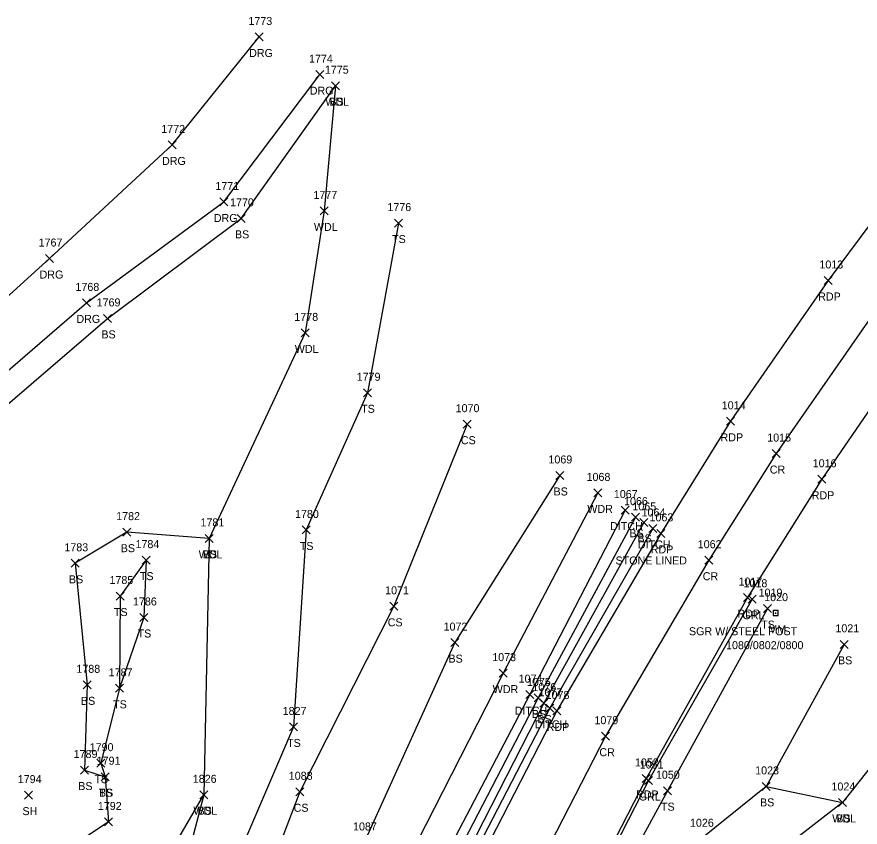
# Model space of a CAD drawing. Extents: x 1551995 to 1555700, y 777276 to 783130.
# Drawn here: x 1554855.8 to 1555066.5, y 778211.4 to 778413.8 of the extents above; entities that cross this region are included whole.
import ezdxf

# ---------------------------------------------------------------- set-up
doc = ezdxf.new("R2010")
doc.units = 0
for name, color, linetype in [('D_A', 7, 'Continuous'), ('D_C', 7, 'Continuous'), ('D_I', 7, 'Continuous'), ('D_TIC', 7, 'Continuous'), ('DD', 7, 'Continuous'), ('L_A', 7, 'Continuous'), ('L_I', 7, 'Continuous'), ('L_TIC', 7, 'Continuous'), ('LAWA', 7, 'Continuous'), ('LELB', 7, 'Continuous'), ('P_A', 7, 'Continuous'), ('P_I', 7, 'Continuous'), ('P_TIC', 7, 'Continuous'), ('PET', 7, 'Continuous'), ('PRC', 7, 'Continuous'), ('R_A', 7, 'Continuous'), ('R_C', 7, 'Continuous'), ('R_I', 7, 'Continuous'), ('R_TIC', 7, 'Continuous'), ('RDG', 7, 'Continuous'), ('RGR', 7, 'Continuous'), ('S_A', 7, 'Continuous'), ('S_C', 7, 'Continuous'), ('S_I', 7, 'Continuous'), ('SRM', 7, 'Continuous')]:
    doc.layers.add(name, color=color, linetype=linetype)

msp = doc.modelspace()

# ---------------------------------------------------------------- linework, layer by layer
at = {"layer": 'D_TIC'}
for points in [[(1555006.77, 778289.58), (1555008.77, 778291.58)], [(1555008.77, 778289.58), (1555006.77, 778291.58)], [(1555013.72, 778284.98), (1555015.72, 778286.98)], [(1555015.72, 778284.98), (1555013.72, 778286.98)], [(1554982.94, 778243.46), (1554984.94, 778245.46)], [(1554984.94, 778243.46), (1554982.94, 778245.46)], [(1554987.93, 778240.04), (1554989.93, 778242.04)], [(1554989.93, 778240.04), (1554987.93, 778242.04)]]:
    msp.add_lwpolyline(points, dxfattribs=at)
at = {"layer": 'DD'}
for points in [[(1555007.77, 778290.58), (1554983.94, 778244.46), (1554960.71, 778200.12), (1554946.97, 778167.91), (1554938.22, 778146.67)], [(1555014.72, 778285.98), (1554988.93, 778241.04), (1554966.26, 778197.38), (1554951.47, 778164.91), (1554943.03, 778145), (1554942.04, 778145.43), (1554940.77, 778145.78), (1554938.22, 778146.67)]]:
    msp.add_lwpolyline(points, dxfattribs=at)
at = {"layer": 'L_TIC'}
for points in [[(1554934.43, 778395.62), (1554936.43, 778397.62)], [(1554936.43, 778395.62), (1554934.43, 778397.62)], [(1554934.43, 778395.62), (1554936.43, 778397.62)], [(1554936.43, 778395.62), (1554934.43, 778397.62)], [(1554931.57, 778364.34), (1554933.57, 778366.34)], [(1554933.57, 778364.34), (1554931.57, 778366.34)], [(1554910.83, 778362.48), (1554912.83, 778364.48)], [(1554912.83, 778362.48), (1554910.83, 778364.48)], [(1554950.12, 778361.3), (1554952.12, 778363.3)], [(1554952.12, 778361.3), (1554950.12, 778363.3)], [(1554877.45, 778337.48), (1554879.45, 778339.48)], [(1554879.45, 778337.48), (1554877.45, 778339.48)], [(1554926.8, 778333.86), (1554928.8, 778335.86)], [(1554928.8, 778333.86), (1554926.8, 778335.86)], [(1554942.39, 778318.89), (1554944.39, 778320.89)], [(1554944.39, 778318.89), (1554942.39, 778320.89)], [(1554967.28, 778311.04), (1554969.28, 778313.04)], [(1554969.28, 778311.04), (1554967.28, 778313.04)], [(1554990.44, 778298.23), (1554992.44, 778300.23)], [(1554992.44, 778298.23), (1554990.44, 778300.23)], [(1554999.96, 778293.87), (1555001.96, 778295.87)], [(1555001.96, 778293.87), (1554999.96, 778295.87)], [(1555009.39, 778287.8), (1555011.39, 778289.8)], [(1555011.39, 778287.8), (1555009.39, 778289.8)], [(1555011.41, 778286.51), (1555013.41, 778288.51)], [(1555013.41, 778286.51), (1555011.41, 778288.51)], [(1554882.27, 778284.06), (1554884.27, 778286.06)], [(1554884.27, 778284.06), (1554882.27, 778286.06)], [(1554927.06, 778284.61), (1554929.06, 778286.61)], [(1554929.06, 778284.61), (1554927.06, 778286.61)], [(1554902.79, 778282.5), (1554904.79, 778284.5)], [(1554904.79, 778282.5), (1554902.79, 778284.5)], [(1554902.79, 778282.5), (1554904.79, 778284.5)], [(1554904.79, 778282.5), (1554902.79, 778284.5)], [(1554869.33, 778276.28), (1554871.33, 778278.28)], [(1554871.33, 778276.28), (1554869.33, 778278.28)], [(1554887.1, 778277.07), (1554889.1, 778279.07)], [(1554889.1, 778277.07), (1554887.1, 778279.07)], [(1554887.1, 778277.07), (1554889.1, 778279.07)], [(1554889.1, 778277.07), (1554887.1, 778279.07)], [(1554880.6, 778268.1), (1554882.6, 778270.1)], [(1554882.6, 778268.1), (1554880.6, 778270.1)], [(1554949, 778265.53), (1554951, 778267.53)], [(1554951, 778265.53), (1554949, 778267.53)], [(1555042.36, 778264.96), (1555044.36, 778266.96)], [(1555044.36, 778264.96), (1555042.36, 778266.96)], [(1554886.53, 778262.74), (1554888.53, 778264.74)], [(1554888.53, 778262.74), (1554886.53, 778264.74)], [(1554964.18, 778256.46), (1554966.18, 778258.46)], [(1554966.18, 778256.46), (1554964.18, 778258.46)], [(1555061.53, 778256.03), (1555063.53, 778258.03)], [(1555063.53, 778256.03), (1555061.53, 778258.03)], [(1554976.33, 778248.83), (1554978.33, 778250.83)], [(1554978.33, 778248.83), (1554976.33, 778250.83)], [(1554872.34, 778245.91), (1554874.34, 778247.91)], [(1554874.34, 778245.91), (1554872.34, 778247.91)], [(1554880.41, 778245.04), (1554882.41, 778247.04)], [(1554882.41, 778245.04), (1554880.41, 778247.04)], [(1554880.41, 778245.04), (1554882.41, 778247.04)], [(1554882.41, 778245.04), (1554880.41, 778247.04)], [(1554985.01, 778242.63), (1554987.01, 778244.63)], [(1554987.01, 778242.63), (1554985.01, 778244.63)], [(1554986.42, 778241.35), (1554988.42, 778243.35)], [(1554988.42, 778241.35), (1554986.42, 778243.35)], [(1554923.89, 778235.39), (1554925.89, 778237.39)], [(1554925.89, 778235.39), (1554923.89, 778237.39)], [(1554875.74, 778226.33), (1554877.74, 778228.33)], [(1554877.74, 778226.33), (1554875.74, 778228.33)], [(1554871.65, 778224.62), (1554873.65, 778226.62)], [(1554873.65, 778224.62), (1554871.65, 778226.62)], [(1554876.84, 778222.95), (1554878.84, 778224.95)], [(1554878.84, 778222.95), (1554876.84, 778224.95)], [(1554876.84, 778222.95), (1554878.84, 778224.95)], [(1554878.84, 778222.95), (1554876.84, 778224.95)], [(1554925.49, 778219.19), (1554927.49, 778221.19)], [(1554927.49, 778219.19), (1554925.49, 778221.19)], [(1555017.33, 778219.45), (1555019.33, 778221.45)], [(1555019.33, 778219.45), (1555017.33, 778221.45)], [(1555042.05, 778220.53), (1555044.05, 778222.53)], [(1555044.05, 778220.53), (1555042.05, 778222.53)], [(1555042.05, 778220.53), (1555044.05, 778222.53)], [(1555044.05, 778220.53), (1555042.05, 778222.53)], [(1554857.68, 778218.35), (1554859.68, 778220.35)], [(1554859.68, 778218.35), (1554857.68, 778220.35)], [(1554901.47, 778218.43), (1554903.47, 778220.43)], [(1554903.47, 778218.43), (1554901.47, 778220.43)], [(1554901.47, 778218.43), (1554903.47, 778220.43)], [(1554903.47, 778218.43), (1554901.47, 778220.43)], [(1555061.11, 778216.51), (1555063.11, 778218.51)], [(1555063.11, 778216.51), (1555061.11, 778218.51)], [(1555061.11, 778216.51), (1555063.11, 778218.51)], [(1555063.11, 778216.51), (1555061.11, 778218.51)], [(1554877.69, 778211.64), (1554879.69, 778213.64)], [(1554879.69, 778211.64), (1554877.69, 778213.64)]]:
    msp.add_lwpolyline(points, dxfattribs=at)
at = {"layer": 'LAWA'}
for points in [[(1554935.43, 778396.62), (1554932.57, 778365.34), (1554927.8, 778334.86), (1554903.79, 778283.5), (1554902.47, 778219.43), (1554891.48, 778177.56), (1554886.36, 778149.25), (1554864.38, 778127.13), (1554855.54, 778103.27), (1554855.62, 778088.16), (1554832.42, 778095.39), (1554813.64, 778080.72)], [(1555000.96, 778294.87), (1554977.33, 778249.83), (1554953.65, 778203.43), (1554934.13, 778158.37), (1554921.74, 778129.69), (1554915, 778109.12), (1554905.48, 778082.18), (1554899.62, 778064.01), (1554889.87, 778042.09), (1554882.71, 778000.01), (1554871.69, 777971.47), (1554868.37, 777961.54), (1554861.96, 777920.45), (1554858.53, 777878.75), (1554855.37, 777850.35), (1554848.67, 777827.4), (1554836.72, 777779.63)], [(1555085.12, 778246.6), (1555062.11, 778217.51), (1555036.75, 778197.89), (1555030.02, 778178.79), (1555023.09, 778154.13), (1555005.22, 778133.85), (1555000.72, 778121.06), (1554983.85, 778091.44), (1554975.19, 778092.03), (1554970.99, 778074.93), (1554967.22, 778059.88), (1554967.17, 778023.98), (1554956.28, 777979.25), (1554949.24, 777950.5), (1554942.15, 777917.97), (1554937.88, 777884.35), (1554924.17, 777845.95), (1554911.99, 777797.39)]]:
    msp.add_lwpolyline(points, dxfattribs=at)
at = {"layer": 'LELB'}
for points in [[(1554773.41, 778171.97), (1554778.92, 778183.17), (1554784.77, 778193.93), (1554789.2, 778196.75), (1554789.17, 778207.67), (1554793.35, 778231.14), (1554800.41, 778253.93), (1554805.57, 778264.25), (1554823.29, 778287.72), (1554845.67, 778310.36), (1554878.45, 778338.48), (1554911.83, 778363.48), (1554935.43, 778396.62)], [(1554951.12, 778362.3), (1554943.39, 778319.89), (1554928.06, 778285.61), (1554924.89, 778236.39), (1554911.42, 778204.9), (1554899.21, 778179.16), (1554886.36, 778149.25)], [(1554968.28, 778312.04), (1554950, 778266.53), (1554926.49, 778220.19), (1554908.96, 778174.42), (1554896.48, 778148.26), (1554883.58, 778119.09), (1554877.33, 778100.58), (1554861.43, 778063.06), (1554849.04, 778068.43), (1554838.51, 778079.97)], [(1554991.44, 778299.23), (1554965.18, 778257.46), (1554942.56, 778207.52), (1554927.41, 778168.06), (1554913.27, 778138.26), (1554902.03, 778109.91)], [(1555010.39, 778288.8), (1554986.01, 778243.63), (1554962.9, 778199.03), (1554948.43, 778166.96), (1554940.77, 778145.78), (1554936.48, 778136)], [(1555012.41, 778287.51), (1554987.42, 778242.35), (1554964.94, 778198.34), (1554949.46, 778165.73), (1554942.04, 778145.43), (1554936.48, 778136), (1554931.2, 778126.36), (1554925.41, 778115.96), (1554925.69, 778108.05), (1554919.03, 778090.31), (1554918.44, 778089.95), (1554914.24, 778077.2), (1554901.57, 778039.07), (1554894.39, 777997.12), (1554883.88, 777962.74), (1554876.08, 777918.21), (1554866.8, 777876.47), (1554857.76, 777827.38), (1554846.36, 777775.83)], [(1554903.79, 778283.5), (1554883.27, 778285.06), (1554870.33, 778277.28), (1554873.34, 778246.91), (1554872.65, 778225.62), (1554877.84, 778223.95)], [(1554888.1, 778278.07), (1554881.6, 778269.1), (1554881.41, 778246.04), (1554876.74, 778227.33), (1554877.84, 778223.95), (1554878.69, 778212.64), (1554860.35, 778200.47), (1554839.38, 778199.43), (1554828.22, 778212.97), (1554822.86, 778217.91), (1554830.88, 778220.88), (1554825.41, 778230.38), (1554822.91, 778242.56), (1554824.36, 778250.86)], [(1554888.1, 778278.07), (1554887.53, 778263.74), (1554881.41, 778246.04)], [(1555043.36, 778265.96), (1555018.33, 778220.45), (1555000.7, 778188.06), (1554983.47, 778153.1), (1554971.68, 778123.43), (1554963.77, 778100.46)], [(1555062.53, 778257.03), (1555043.05, 778221.53), (1555026.82, 778208.44), (1555019.74, 778198.68), (1555014.58, 778191.04), (1555012.64, 778162.24), (1554995.57, 778139.61), (1554992.44, 778124.79), (1554979.79, 778115.45), (1554974.95, 778099.31), (1554975.19, 778092.03)], [(1555043.05, 778221.53), (1555062.11, 778217.51)], [(1554853.05, 778176.97), (1554866.72, 778175.96), (1554883.84, 778187.36), (1554902.47, 778219.43)]]:
    msp.add_lwpolyline(points, dxfattribs=at)
at = {"layer": 'P_TIC'}
for points in [[(1555057.53, 778346.95), (1555059.53, 778348.95)], [(1555059.53, 778346.95), (1555057.53, 778348.95)], [(1555033.13, 778311.76), (1555035.13, 778313.76)], [(1555035.13, 778311.76), (1555033.13, 778313.76)], [(1555044.49, 778303.7), (1555046.49, 778305.7)], [(1555046.49, 778303.7), (1555044.49, 778305.7)], [(1555055.92, 778297.28), (1555057.92, 778299.28)], [(1555057.92, 778297.28), (1555055.92, 778299.28)], [(1555015.69, 778283.76), (1555017.69, 778285.76)], [(1555017.69, 778283.76), (1555015.69, 778285.76)], [(1555027.73, 778277.05), (1555029.73, 778279.05)], [(1555029.73, 778277.05), (1555027.73, 778279.05)], [(1555037.33, 778267.72), (1555039.33, 778269.72)], [(1555039.33, 778267.72), (1555037.33, 778269.72)], [(1554989.68, 778239.38), (1554991.68, 778241.38)], [(1554991.68, 778239.38), (1554989.68, 778241.38)], [(1555001.89, 778233.08), (1555003.89, 778235.08)], [(1555003.89, 778233.08), (1555001.89, 778235.08)], [(1555012, 778222.52), (1555014, 778224.52)], [(1555014, 778222.52), (1555012, 778224.52)]]:
    msp.add_lwpolyline(points, dxfattribs=at)
at = {"layer": 'PET'}
for points in [[(1555086.85, 778385.99), (1555058.53, 778347.95), (1555034.13, 778312.76), (1555016.69, 778284.76), (1554990.68, 778240.38), (1554968.05, 778196.33), (1554953.03, 778164.25), (1554940.37, 778132.83), (1554930.99, 778106.02), (1554923.77, 778083.63), (1554909.85, 778036.75), (1554900.04, 777995.37), (1554891.67, 777961.45), (1554881.9, 777917.03), (1554872.92, 777875.28), (1554862.74, 777826.66), (1554851.19, 777774.32)], [(1555108.52, 778369.81), (1555078.86, 778330.23), (1555056.92, 778298.28), (1555038.33, 778268.72), (1555013, 778223.52), (1554996, 778190.4), (1554978.91, 778154.53), (1554967.24, 778125.11), (1554957.25, 778096.67), (1554950.17, 778073.38), (1554937.06, 778028.22), (1554926.8, 777988.52), (1554918.72, 777954.59), (1554908.46, 777910.08), (1554899.75, 777869.14), (1554889.9, 777822.39), (1554877.4, 777767.74)]]:
    msp.add_lwpolyline(points, dxfattribs=at)
at = {"layer": 'PRC'}
msp.add_lwpolyline([(1555098.33, 778377.48), (1555069.71, 778339.49), (1555045.49, 778304.7), (1555028.73, 778278.05), (1555002.89, 778234.08), (1554980, 778189.5), (1554966.22, 778159.18), (1554954.38, 778129.46), (1554944.07, 778101.03), (1554941.59, 778092.54), (1554937.34, 778078.77), (1554924.27, 778032.77), (1554914.16, 777991.62), (1554905.84, 777957.86), (1554895.98, 777913.96), (1554886.88, 777872.59), (1554876.72, 777824.26), (1554864.6, 777770.35)], dxfattribs=at)
at = {"layer": 'R_TIC'}
for points in [[(1554915.32, 778407.8), (1554917.32, 778409.8)], [(1554917.32, 778407.8), (1554915.32, 778409.8)], [(1554930.47, 778398.39), (1554932.47, 778400.39)], [(1554932.47, 778398.39), (1554930.47, 778400.39)], [(1554893.55, 778380.82), (1554895.55, 778382.82)], [(1554895.55, 778380.82), (1554893.55, 778382.82)], [(1554906.49, 778366.57), (1554908.49, 778368.57)], [(1554908.49, 778366.57), (1554906.49, 778368.57)], [(1554862.94, 778352.44), (1554864.94, 778354.44)], [(1554864.94, 778352.44), (1554862.94, 778354.44)], [(1554872.15, 778341.35), (1554874.15, 778343.35)], [(1554874.15, 778341.35), (1554872.15, 778343.35)], [(1555038.56, 778267.3), (1555040.56, 778269.3)], [(1555040.56, 778267.3), (1555038.56, 778269.3)], [(1555012.62, 778222), (1555014.62, 778224)], [(1555014.62, 778222), (1555012.62, 778224)]]:
    msp.add_lwpolyline(points, dxfattribs=at)
at = {"layer": 'RDG'}
for points in [[(1554731.76, 777736.57), (1554744.54, 777760.39), (1554749.58, 777791.25), (1554744.63, 777884.27), (1554742.18, 777937.77), (1554733.78, 777989.36), (1554731.62, 778029.74), (1554732.87, 778072.64), (1554738.87, 778112.72), (1554741.1, 778122.89), (1554752.14, 778165.58), (1554757.04, 778182.47), (1554765.14, 778213.69), (1554774.89, 778246.18), (1554785.77, 778269.3), (1554800.7, 778290.2), (1554833.81, 778326.22), (1554863.94, 778353.44), (1554894.55, 778381.82), (1554916.32, 778408.8)], [(1554765.41, 777786.83), (1554760.87, 777887.93), (1554755.21, 777940.6), (1554748.12, 777988.97), (1554746.63, 778028.6), (1554748.07, 778068.94), (1554755.05, 778099.35), (1554759.31, 778115.55), (1554764.29, 778135.87), (1554767.84, 778151.77), (1554770.94, 778162.89), (1554771.35, 778163.02), (1554773.41, 778171.97), (1554775.55, 778183.39), (1554780.94, 778209.88), (1554780.41, 778210.35), (1554788.23, 778232), (1554795.94, 778253.78), (1554801.81, 778267.78), (1554821.53, 778293.59), (1554841.19, 778314.82), (1554873.15, 778342.35), (1554907.49, 778367.57), (1554931.47, 778399.39)]]:
    msp.add_lwpolyline(points, dxfattribs=at)
at = {"layer": 'RGR'}
msp.add_lwpolyline([(1555039.56, 778268.3), (1555013.62, 778223), (1554996.63, 778189.88), (1554979.88, 778154.08), (1554968.24, 778124.65), (1554958.2, 778096.32), (1554950.97, 778072.94), (1554937.27, 778027.95), (1554927.65, 777988.1), (1554919.66, 777954.37), (1554909.72, 777910.11), (1554900.5, 777868.18), (1554890.69, 777822.54), (1554878.36, 777767.59), (1554870.52, 777731.32), (1554860.9, 777689.38), (1554849.55, 777645.14), (1554835.81, 777600.33), (1554822.79, 777564.15), (1554817.07, 777548.72), (1554816.7, 777536.06)], dxfattribs=at)
at = {"layer": 'SRM'}
for p, q in [((1555046.04, 778265.48), (1555044.79, 778265.48)), ((1555044.79, 778265.48), (1555044.79, 778264.23)), ((1555046.04, 778265.48), (1555044.79, 778265.48)), ((1555044.79, 778265.48), (1555044.79, 778264.23)), ((1555046.04, 778264.23), (1555046.04, 778265.48)), ((1555046.04, 778264.23), (1555046.04, 778265.48)), ((1555044.79, 778264.23), (1555046.04, 778264.23)), ((1555044.79, 778264.23), (1555046.04, 778264.23))]:
    msp.add_line(p, q, dxfattribs=at)
msp.add_circle((1555045.39, 778264.82), 0.0833, dxfattribs=at)

# ---------------------------------------------------------------- texts
at = {"layer": 'D_A'}
for p in [(1555004.01, 778285.58), (1555010.96, 778280.98), (1554980.17, 778239.46), (1554985.16, 778236.04)]:
    msp.add_text('DITCH', height=2, dxfattribs=at).set_placement(p)
at = {"layer": 'D_C'}
msp.add_text('STONE LINED', height=2, dxfattribs=at).set_placement((1555005.39, 778276.98))
at = {"layer": 'D_I'}
for s, p in [('1067', (1555004.95, 778293.58)), ('1064', (1555011.9, 778288.98)), ('1074', (1554981.16, 778247.46)), ('1077', (1554986.16, 778244.04))]:
    msp.add_text(s, height=2, dxfattribs=at).set_placement(p)
at = {"layer": 'L_A'}
for s, p in [('WDL', (1554932.85, 778391.62)), ('BS', (1554933.87, 778391.62)), ('WDL', (1554929.99, 778360.34)), ('BS', (1554910.27, 778358.48)), ('TS', (1554949.53, 778357.3)), ('BS', (1554876.89, 778333.48)), ('WDL', (1554925.22, 778329.86)), ('TS', (1554941.8, 778314.89)), ('CS', (1554966.72, 778307.04)), ('BS', (1554989.88, 778294.23)), ('WDR', (1554998.32, 778289.87)), ('BS', (1555008.83, 778283.8)), ('BS', (1555010.85, 778282.51)), ('BS', (1554881.72, 778280.06)), ('TS', (1554926.47, 778280.61)), ('WDL', (1554901.2, 778278.5)), ('BS', (1554902.23, 778278.5)), ('BS', (1554868.77, 778272.28)), ('TS', (1554886.51, 778273.07)), ('TS', (1554886.51, 778273.07)), ('TS', (1554880.01, 778264.1)), ('CS', (1554948.44, 778261.53)), ('TS', (1555041.77, 778260.96)), ('TS', (1554885.94, 778258.74)), ('BS', (1554963.62, 778252.46)), ('BS', (1555060.98, 778252.03)), ('WDR', (1554974.69, 778244.83)), ('BS', (1554871.78, 778241.91)), ('TS', (1554879.82, 778241.04)), ('TS', (1554879.82, 778241.04)), ('BS', (1554984.45, 778238.63)), ('BS', (1554985.86, 778237.35)), ('TS', (1554923.3, 778231.39)), ('TS', (1554875.15, 778222.33)), ('BS', (1554871.1, 778220.62)), ('TS', (1554876.25, 778218.95)), ('BS', (1554876.28, 778218.95)), ('BS', (1555041.49, 778216.53)), ('BS', (1555041.49, 778216.53)), ('WDL', (1554899.89, 778214.43)), ('BS', (1554900.92, 778214.43)), ('CS', (1554924.93, 778215.19)), ('TS', (1555016.74, 778215.45)), ('SH', (1554857.17, 778214.35)), ('WDL', (1555059.53, 778212.51)), ('BS', (1555060.55, 778212.51))]:
    msp.add_text(s, height=2, dxfattribs=at).set_placement(p)
at = {"layer": 'L_I'}
for s, p in [('1775', (1554932.74, 778399.62)), ('1775', (1554932.74, 778399.62)), ('1777', (1554929.88, 778368.34)), ('1770', (1554909.05, 778366.48)), ('1776', (1554948.37, 778365.3)), ('1769', (1554875.7, 778341.48)), ('1778', (1554925.11, 778337.86)), ('1779', (1554940.69, 778322.89)), ('1070', (1554965.42, 778315.04)), ('1069', (1554988.61, 778302.23)), ('1068', (1554998.14, 778297.87)), ('1066', (1555007.51, 778291.8)), ('1065', (1555009.59, 778290.51)), ('1780', (1554925.28, 778288.61)), ('1782', (1554880.58, 778288.06)), ('1781', (1554901.66, 778286.5)), ('1781', (1554901.66, 778286.5)), ('1783', (1554867.64, 778280.28)), ('1784', (1554885.41, 778281.07)), ('1784', (1554885.41, 778281.07)), ('1785', (1554878.91, 778272.1)), ('1071', (1554947.8, 778269.53)), ('1019', (1555041.14, 778268.96)), ('1786', (1554884.78, 778266.74)), ('1072', (1554962.41, 778260.46)), ('1021', (1555060.33, 778260.03)), ('1073', (1554974.56, 778252.83)), ('1788', (1554870.64, 778249.91)), ('1787', (1554878.71, 778249.04)), ('1787', (1554878.71, 778249.04)), ('1075', (1554983.24, 778246.63)), ('1076', (1554984.6, 778245.35)), ('1827', (1554922.2, 778239.39)), ('1790', (1554873.96, 778230.33)), ('1789', (1554869.95, 778228.62)), ('1791', (1554875.71, 778226.95)), ('1791', (1554875.71, 778226.95)), ('1088', (1554923.72, 778223.19)), ('1050', (1555015.47, 778223.45)), ('1023', (1555040.28, 778224.53)), ('1023', (1555040.28, 778224.53)), ('1794', (1554855.99, 778222.35)), ('1826', (1554899.73, 778222.43)), ('1826', (1554899.73, 778222.43)), ('1024', (1555059.34, 778220.51)), ('1024', (1555059.34, 778220.51)), ('1792', (1554876, 778215.64)), ('1087', (1554939.78, 778210.52)), ('1026', (1555023.99, 778211.44))]:
    msp.add_text(s, height=2, dxfattribs=at).set_placement(p)
at = {"layer": 'P_A'}
for s, p in [('RDP', (1555056.02, 778342.95)), ('RDP', (1555031.62, 778307.76)), ('CR', (1555043.93, 778299.7)), ('RDP', (1555054.41, 778293.28)), ('RDP', (1555014.18, 778279.76)), ('CR', (1555027.17, 778273.05)), ('RDP', (1555035.81, 778263.72)), ('RDP', (1554988.17, 778235.38)), ('CR', (1555001.33, 778229.08)), ('RDP', (1555010.49, 778218.52))]:
    msp.add_text(s, height=2, dxfattribs=at).set_placement(p)
at = {"layer": 'P_I'}
for s, p in [('1013', (1555056.33, 778350.95)), ('1014', (1555031.92, 778315.76)), ('1015', (1555043.29, 778307.7)), ('1016', (1555054.66, 778301.28)), ('1063', (1555013.87, 778287.76)), ('1062', (1555025.92, 778281.05)), ('1017', (1555036.12, 778271.72)), ('1078', (1554987.91, 778243.38)), ('1079', (1555000.11, 778237.08)), ('1052', (1555010.23, 778226.52))]:
    msp.add_text(s, height=2, dxfattribs=at).set_placement(p)
at = {"layer": 'R_A'}
for s, p in [('DRG', (1554913.81, 778403.8)), ('DRG', (1554928.96, 778394.39)), ('DRG', (1554892.04, 778376.82)), ('DRG', (1554904.98, 778362.57)), ('DRG', (1554861.43, 778348.44)), ('DRG', (1554870.64, 778337.35)), ('GRL', (1555037.11, 778263.3)), ('GRL', (1555011.17, 778218))]:
    msp.add_text(s, height=2, dxfattribs=at).set_placement(p)
at = {"layer": 'R_C'}
msp.add_text('SGR W/ STEEL POST', height=2, dxfattribs=at).set_placement((1555023.73, 778259.3))
at = {"layer": 'R_I'}
for s, p in [('1773', (1554913.63, 778411.8)), ('1774', (1554928.78, 778402.39)), ('1772', (1554891.86, 778384.82)), ('1771', (1554905.37, 778370.57)), ('1767', (1554861.2, 778356.44)), ('1768', (1554870.41, 778345.35)), ('1018', (1555037.36, 778271.3)), ('1051', (1555011.42, 778226))]:
    msp.add_text(s, height=2, dxfattribs=at).set_placement(p)
at = {"layer": 'S_A'}
msp.add_text('MM', height=2, dxfattribs=at).set_placement((1555043.58, 778259.82))
at = {"layer": 'S_C'}
msp.add_text('1080/0802/0800', height=2, dxfattribs=at).set_placement((1555033, 778255.82))
at = {"layer": 'S_I'}
msp.add_text('1020', height=2, dxfattribs=at).set_placement((1555042.53, 778267.82))

doc.saveas('drawing.dxf')
